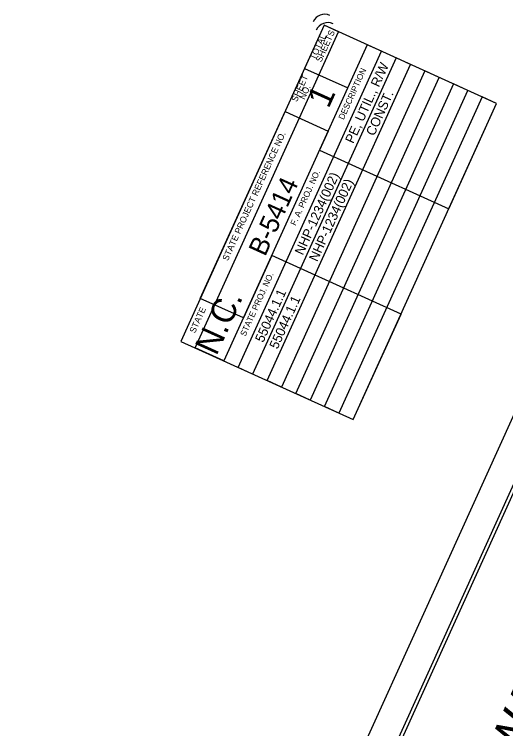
# Model space of a CAD drawing. Extents: x 1744741 to 2014229, y 466994 to 951338.
# Drawn here: x 2010049 to 2010827, y 477045 to 478176 of the extents above; entities that cross this region are included whole.
import ezdxf

# ---------------------------------------------------------------- set-up
doc = ezdxf.new("R2010")
doc.units = 0
for name, color, linetype in [('Sheet Data Field CELL', 7, 'Continuous'), ('Sheet Plan CELL', 7, 'Continuous'), ('Sheet Plot Border Inside CELL', 7, 'Continuous'), ('Sheet Plot Border Outside CELL', 7, 'Continuous'), ('Sheet Sticker Preliminary CELL', 7, 'Continuous'), ('Sheet Title CELL', 7, 'Continuous')]:
    doc.layers.add(name, color=color, linetype=linetype)

msp = doc.modelspace()

# ---------------------------------------------------------------- linework, layer by layer
at = {"layer": 'Sheet Plan CELL'}
msp.add_lwpolyline([(2011066.5, 477919.9), (2009673.2, 474845.9), (2011825, 473870.6), (2013218.3, 476944.6)], close=True, dxfattribs=at)
at = {"layer": 'Sheet Plot Border Inside CELL'}
msp.add_lwpolyline([(2011687.5, 473553.7), (2013235, 476967.9), (2011073, 477947.8), (2009525.5, 474533.7)], close=True, dxfattribs=at)
at = {"layer": 'Sheet Plot Border Outside CELL'}
msp.add_lwpolyline([(2011716.4, 473508.5), (2013280.2, 476958.5), (2011036.2, 477975.6), (2009472.4, 474525.6)], close=True, dxfattribs=at)
at = {"layer": 'Sheet Title CELL'}
msp.add_lwpolyline([(2010585.6, 477534.3), (2010812.7, 478035.2), (2010789.9, 478045.5), (2010562.8, 477544.6), (2010540.1, 477554.9), (2010767.2, 478055.9), (2010744.4, 478066.2), (2010517.3, 477565.2), (2010494.5, 477575.6), (2010721.6, 478076.5), (2010698.8, 478086.8), (2010471.8, 477585.9), (2010449, 477596.2), (2010676, 478097.1), (2010653.3, 478107.5), (2010426.2, 477606.5), (2010403.5, 477616.8), (2010630.5, 478117.8), (2010607.7, 478128.1), (2010380.7, 477627.2), (2010335.1, 477647.8), (2010562.2, 478148.7), (2010539.4, 478159.1), (2010312.4, 477658.1), (2010585.6, 477534.3), (2010661.3, 477701.2), (2010456.4, 477794.1), (2010411.7, 477695.5), (2010343.3, 477726.4), (2010477.5, 478022.5), (2010545.8, 477991.5), (2010532, 477961.1), (2010737, 477868.2), (2010812.7, 478035.2), (2010539.4, 478159.1), (2010508.5, 478090.8), (2010576.8, 478059.8)], dxfattribs=at)
for centre in [(2010540.3, 478156.5), (2010545.3, 478143.2)]:
    msp.add_arc(centre, 20, 65.6171, 155.6171, dxfattribs=at)

# ---------------------------------------------------------------- texts
at = {"layer": 'Sheet Data Field CELL'}
for s, height, p in [('PE, UTIL., R/W', 15, (2010585.7, 477970.6)), ('CONST.', 15, (2010618.7, 477982.6)), ('B-5414', 30, (2010446, 477791.5)), ('NHP-1234(002)', 15, (2010505.8, 477793.8)), ('NHP-1234(002)', 15, (2010528.5, 477783.5)), ('55044.1.1', 15, (2010443, 477655.3)), ('55044.1.1', 15, (2010465.7, 477644.9))]:
    msp.add_text(s, height=height, rotation=65.6171, dxfattribs=at).set_placement(p)
at = {"layer": 'Sheet Sticker Preliminary CELL'}
for s, p in [('2018 ROADWAY ENGLISH ', (2010680.7, 476622.8)), ('STANDARD DRAWINGS', (2010748.7, 476622.9))]:
    msp.add_text(s, height=56.25, rotation=65.6171, dxfattribs=at).set_placement(p)
at = {"layer": 'Sheet Title CELL'}
for s, height, p in [('TOTAL', 10, (2010525.4, 478103.2)), ('SHEETS', 10, (2010534.8, 478099.7)), ('DESCRIPTION', 9.6, (2010570.4, 478008.6)), ('SHEET', 10, (2010496.2, 478036.9)), ('NO.', 10, (2010508.6, 478040.4)), ('1', 38.7, (2010546.4, 478026)), ('STATE PROJECT REFERENCE NO.', 10, (2010386.9, 477784.9)), ('F. A. PROJ. NO.', 9.6, (2010494.3, 477840.8)), ('STATE PROJ. NO.', 9.6, (2010414.8, 477665.4)), ('N.C.', 38.7, (2010368.8, 477634.2)), ('STATE', 10, (2010334.9, 477670.4))]:
    msp.add_text(s, height=height, rotation=65.6171, dxfattribs=at).set_placement(p)

doc.saveas('drawing.dxf')
